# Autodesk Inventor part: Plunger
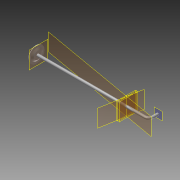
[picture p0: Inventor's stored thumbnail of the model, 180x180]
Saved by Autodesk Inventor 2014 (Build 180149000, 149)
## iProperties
Created: 2009-03
Part Number: Plunger
Document SubType Name: Modeling
Designer: tangg
Density: 8.03 g/cm^3
Material: Stainless Steel, Austenitic
Mass: 116.743 g
Surface Area: 101.946 cm^2
Volume: 14.5383 cm^3
Appearance: Steel
Author: tangg
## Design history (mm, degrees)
sketch "Sketch1"
  geometry: L1 (0, 0)-(290, 0); L2 (300, 10)-(300, 25); A1 r 10 centre (290, 10) between (290, 0) and (300, 10); 1 further point
  constraints: 4 end point, 2 point on circle, 2 point on line, 2 tangent, 1 centre point, 1 horizontal, 1 perpendicular
  dimensions: "d0" = 300 distance of L1.start point (300, 0); "d1" = 25 distance of point (300, 0) L2.end; "d2" = 10 radius of A1
workplane "Work Plane1"
sketch "Sketch2"
  geometry: C1 r 3.5 at (0, 0); 3 further points
  constraints: 1 centre point, 1 coincident, 1 other
  dimensions: "d3" = 7 diameter of C1
sweep "Sweep1" sketch "Sketch2" dims "d4" = 0
sketch "Sketch3"
  geometry: L1 (-4.358, -21.225)-(-2.799, -21.225); L2 (-2.799, -21.225)-(-2.799, -15.815); L3 (-2.799, -15.815)-(-4.358, -15.815); L4 (-4.358, -15.815)-(-4.358, -21.225); L5 (0, 0)-(-1.559, 0); L6 (-1.559, 0)-(-1.559, -10.63); L7 (-1.559, -10.63)-(0, -10.63); L8 (0, -10.63)-(0, 0); L9 (-4.358, -15.815)-(-1.559, -10.63); L10 (-2.799, -15.815)-(0, -10.63)
  constraints: 20 end point, 5 parallel, 2 horizontal, 2 perpendicular
revolve "Revolution1" sketch "Sketch3" stored, may be unused: angle "d5" = 90 deg
chamfer "Chamfer1" distance "d6" = 1; stored, may be unused: second distance "d7" = 2, angle "d8" = 45 deg
workplane "Work Plane2"
workplane "Work Plane12"
workplane "Work Plane13"
workplane "Work Plane14"
workaxis "Work Axis2"
workplane "Work Plane16"
  workplane "Work Plane15"
split "Split7"
split "Split8"
split "Split9"
body "Solid1"
other parameters: "d18" = -3, "d19" = 3, "d20" = 10 deg, "d21" = 90 deg
